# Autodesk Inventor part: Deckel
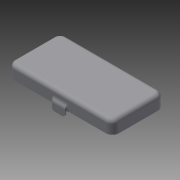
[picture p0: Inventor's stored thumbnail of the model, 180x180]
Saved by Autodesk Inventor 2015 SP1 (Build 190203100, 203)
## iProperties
Created: 2014-11
Part Number: Deckel
Material: Generisch
Document SubType Name: Modeling
Designer: Watson
Density: 1 g/cm^3
Appearance: Vorgabe
Author: Watson
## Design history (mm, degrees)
sketch "Skizze1"
  geometry: L1 (-40, -20)-(40, -20); L2 (40, -20)-(40, 20); L3 (40, 20)-(-40, 20); L4 (-40, 20)-(-40, -20); L5 (-40, -20)-(40, 20); L6 (40, -20)-(-40, 20); 1 further point
  constraints: 12 end point, 2 midpoint, 2 parallel, 1 horizontal, 1 perpendicular
  dimensions: "d0" = 80 distance of L2.end L3.end; "d1" = 40 distance of L1.end L2.end
extrude "Extrusion1" new body sketch "Skizze1" distance "d2" = 10; taper "d3" = 0 deg
fillet "Rundung1" dims "d4" = 5
fillet "Rundung2" dims "d5" = 3
feature "Wandung1" dims "d38" = 1.2
sketch "Skizze2"
  geometry: L1 (70, 0)-(0, 0) reference; L2 (64.5, 0)-(56.5, 0); L3 (56.5, 0)-(56.5, -3); L4 (56.5, -3)-(64.5, -3); L5 (64.5, -3)-(64.5, 0); L6 (35, 9.2)-(35, -13.2) reference; L7 (64.5, 0)-(56.5, 0); L8 (56.5, 0)-(56.5, 10.5); L9 (56.5, 10.5)-(64.5, 10.5); L10 (64.5, 10.5)-(64.5, 0); 1 further point
  constraints: 16 end point, 4 parallel, 2 horizontal, 2 perpendicular, 1 point on line
  dimensions: "d6" = 3 distance of L2.end L3.end; "d7" = 8 distance of L3.end L4.end; "d8" = 21.5 distance between parallel lines of L6 L3; "d9" = 10.5 distance of L2.end L8.end
extrude "Extrusion2" join sketch "Skizze2" distance "d10" = 7; taper "d11" = 0 deg
sketch "Skizze3"
  geometry: L1 (0, 0)-(-3, 0) reference; L2 (-3, 0)-(-3, 7) reference; C1 r 2 at (7.5, 4); 1 further point
  constraints: 1 centre point
  dimensions: "d12" = 4 diameter of C1; "d13" = 4 distance from line of C1.centre L1; "d14" = 10.5 distance from line of L2 C1.centre
extrude "Extrusion3" cut sketch "Skizze3" stored distance "d15" = 6; taper "d16" = 0 deg
sketch "Skizze4"
  geometry: L1 (0, 0)-(0, -5) reference; L2 (0, 0)-(10.5, 0) reference; L3 (10.5, 0)-(10.5, 7) reference; L4 (10.5, 0.5)-(0, 0.5); L5 (0, 0.5)-(0, 0); L6 (0, 0)-(10.5, 0); L7 (10.5, 0)-(10.5, 0.5); 1 further point
  constraints: 8 end point, 2 parallel, 1 horizontal, 1 perpendicular, 1 point on line
  dimensions: "d18" = 0.5 distance between parallel lines of L2 L4
extrude "Extrusion4" cut sketch "Skizze4" stored distance "d19" = 6; taper "d20" = 0 deg
fillet "Rundung4" dims "d21" = 3.5
fillet "Rundung5" dims "d22" = 3
chamfer "Fase2" distance "d29" = 5; stored, may be unused: second distance "d30" = 2, angle "d31" = 60 deg
fillet "Rundung9" dims "d32" = 6
fillet "Rundung10" dims "d33" = 10
fillet "Rundung11" dims "d34" = 4
mirror "Spiegeln1"
fillet "Rundung12" dims "d35" = 0.5
fillet "Rundung13" dims "d36" = 0.5
fillet "Rundung14" dims "d37" = 0.5
sketch "Skizze9"
  geometry: L1 (-15, 0)-(-20, 0) reference; L2 (-20, 0)-(-20, 8.503); L3 (-20, 0)-(-20.5, 0); L4 (-20.5, 0)-(-20.5, -4); L5 (-20.5, -4)-(-21.3, -4); L6 (-21.3, -4)-(-21.3, 2); L7 (-21.3, 2)-(-20, 4.252); 1 further point
  constraints: 12 end point, 3 perpendicular, 2 midpoint, 1 horizontal
  dimensions: "d60" = 4 distance of L3.end L4.end; "d61" = 0.8 distance of L4.end L5.end; "d62" = 0.5 distance of L1.end L3.end; "d64" = 30 deg angle of L2 L7; "d65" = 6 distance of L5.end L6.end
extrude "Extrusion9" join sketch "Skizze9" stored distance "d66" = 10; taper "d67" = 0 deg
sketch "Skizze10"
  geometry: L1 (4, -20.5)-(0, -20.5) reference; L2 (0, -20.5)-(4, -20.5) reference; L3 (4, -21.3)-(4, -20.5) reference; L4 (4, -20.5)-(4, -21.3) reference; L5 (4, -20.5)-(0, -20.5) reference; L6 (3.5, -20.5)-(2.9, -19.9); L7 (2.9, -19.9)-(2.4, -19.9); L8 (4, -21.3)-(-2, -21.3) reference; L9 (2.4, -19.9)-(1.8, -20.5); 1 further point
  constraints: 6 end point, 2 point on line, 1 parallel
  dimensions: "d68" = 0.5 distance from line of L6.start L3; "d69" = 0.6 distance between parallel lines of L1 L7; "d70" = 0.5 distance of L6.end L7.end; "d71" = 45 deg angle of L1 L6; "d72" = 45 deg angle of L1 L9
extrude "Extrusion10" join sketch "Skizze10" stored distance "d73" = 10; taper "d74" = 0 deg
fillet "Rundung17" dims "d75" = 2
fillet "Rundung18" dims "d76" = 4
fillet "Rundung19" dims "d77" = 2
fillet "Rundung20" dims "d78" = 0.2
node "Volumenkörper1"
node "Projizierte Kontur2"
node "Projizierte Kontur3"
